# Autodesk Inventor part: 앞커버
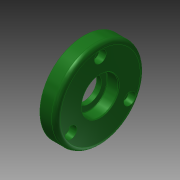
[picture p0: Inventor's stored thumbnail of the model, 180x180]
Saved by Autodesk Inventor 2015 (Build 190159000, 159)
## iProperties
Created: 2015-11
Part Number: 앞커버
Material: 알루미늄 6061
Document SubType Name: Modeling
Designer: mduedu
Density: 1 g/cm^3
Appearance: 매끄러움 - 짙은 산림 녹색
Author: mduedu
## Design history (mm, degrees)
sketch "스케치5"
  geometry: C1 r 30 at (0, 0); 2 further points
  constraints: 2 coincident, 1 centre point
  dimensions: "d66" = 60 diameter of C1
extrude "돌출2" new body sketch "스케치5" distance "d67" = 11; taper "d68" = 0 deg
sketch "스케치6"
  geometry: C1 r 16 at (0, 0); 1 further point
  constraints: 1 centre point, 1 coincident
  dimensions: "d69" = 32 diameter of C1
extrude "돌출3" join sketch "스케치6" distance "d70" = 3; taper "d71" = 0 deg
hole "구멍7" diameter "d98" = 27; stored, may be unused: countersink angle "d102" = 90 deg, drill point angle "d104" = 0 deg; dims "d99" = 6, "d100" = 4, "d101" = 2, "d103" = 3, "d143" = 10, "d144" = 10
hole "구멍8" diameter "d107" = 25; stored, may be unused: countersink angle "d111" = 90 deg, drill point angle "d113" = 0 deg; dims "d105" = 10, "d106" = 10, "d108" = 6, "d109" = 4, "d110" = 2, "d112" = 7.7
hole "구멍9" diameter "d116" = 17; stored, may be unused: countersink angle "d120" = 90 deg, drill point angle "d122" = 0 deg; dims "d114" = 10, "d115" = 10, "d117" = 6, "d118" = 4, "d119" = 2, "d121" = 7.7
chamfer "모따기2" distance "d123" = 0.6; stored, may be unused: second distance "d124" = 2, angle "d125" = 30 deg
fillet "모깎기11" dims "d126" = 0.3
fillet "모깎기13" dims "d128" = 3
fillet "모깎기14" dims "d129" = 3
fillet "모깎기15" dims "d130" = 0.3
sketch "스케치8" dims "d131" = 46
  geometry: 3 further points
  constraints: 2 vertical alignment, 1 coincident, 2 other
hole "구멍10" sketch "스케치8" at (0, 23) diameter "d132" = 4.5; stored, may be unused: countersink angle "d136" = 90 deg, drill point angle "d138" = 0 deg; dims "d133" = 6, "d134" = 8, "d135" = 4.6, "d137" = 7.7
node "솔리드2"
pattern_circular "원형 패턴4" dims angle "d140" = 360 deg
